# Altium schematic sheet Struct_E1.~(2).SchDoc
size 420 x 297 mm; Scale: 1:1; Разраб.: Иванов; Обозначение документа: АБВГ.123456.001 Э3; Пров.: Петров; Утв.: Сидоров; Наименование организации: ОАО "Концерн "МПО-Гидроприбор"; Перв. применение: АБВГ.123456.000; Наименование изделия 1: Плата; Наименование изделия 2: Схема электрическая; Наименование изделия 3: принципиальная; Нач. отд.: Нач. отд.; Фамилия нач. отд.: Сидоров
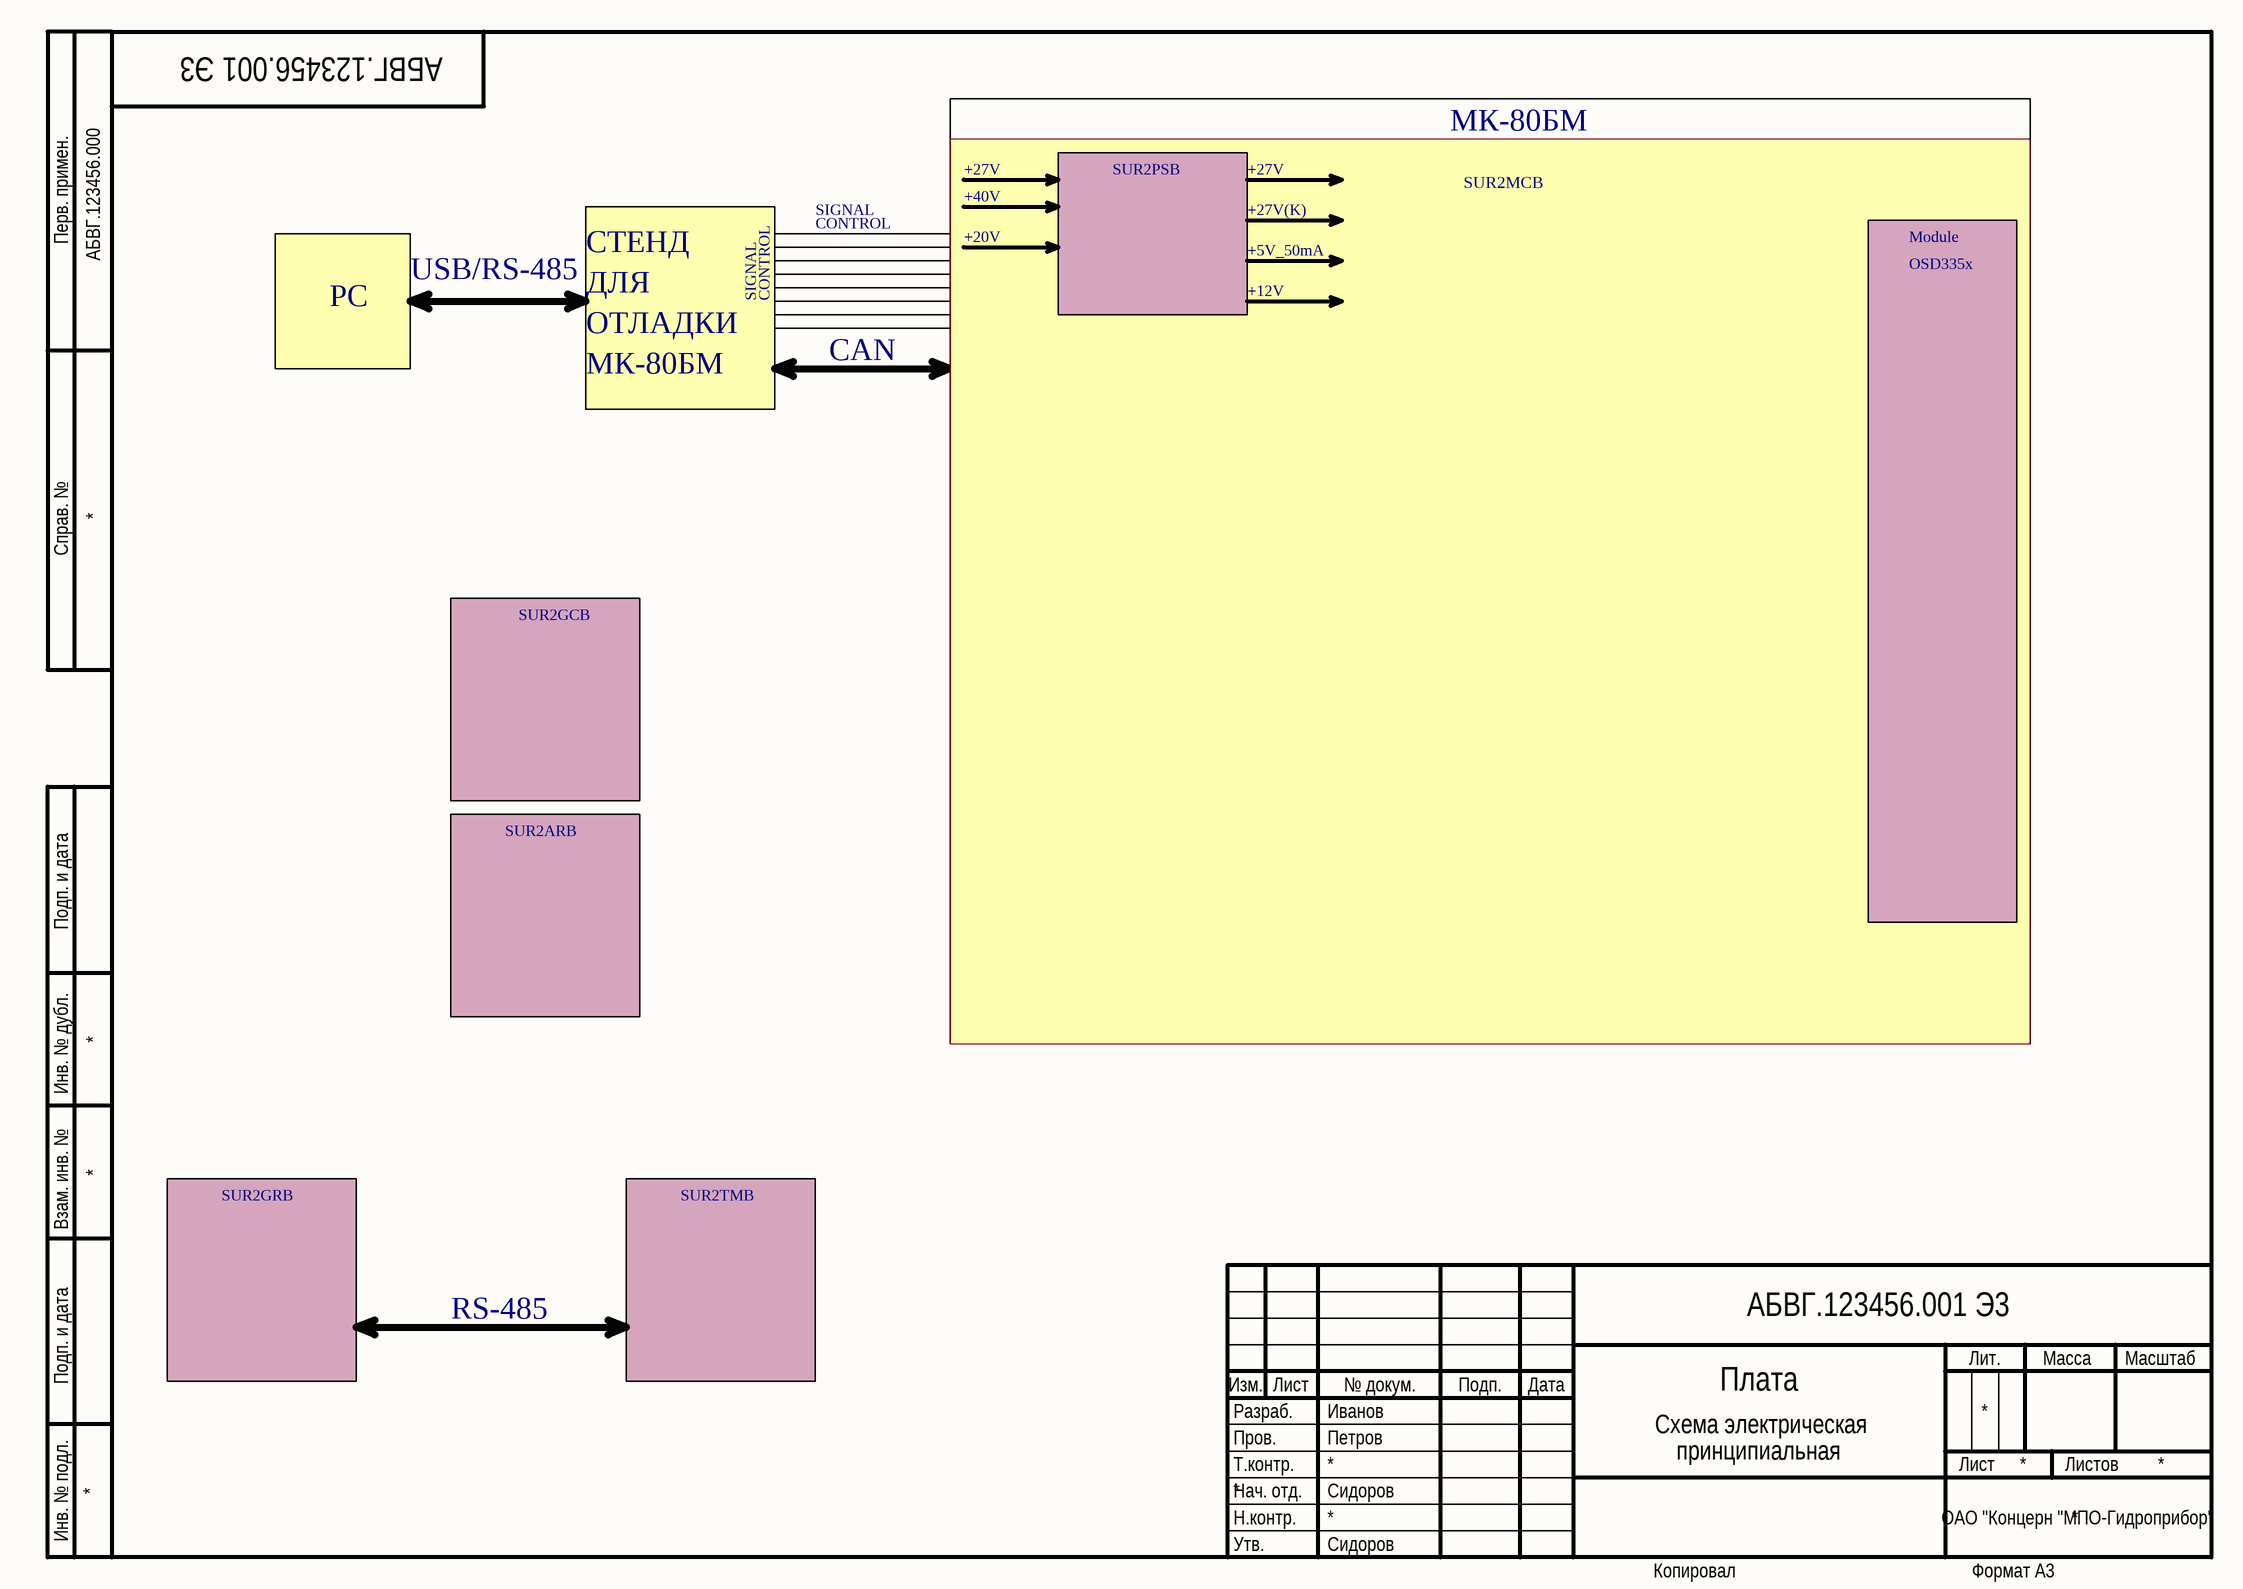
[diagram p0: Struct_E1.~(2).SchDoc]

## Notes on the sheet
- +27V
- SUR2PSB
- МК-80БМ
- SUR2MCB
- СТЕНД
- SIGNAL
- CONTROL
- +40V
- +20V
- +27V(K)
- +5V_50mA
- Module
- PC
- USB/RS-485
- ДЛЯ
- +12V
- OSD335x
- ОТЛАДКИ
- CAN
- SUR2GCB
- SUR2ARB
- SUR2GRB
- SUR2TMB
- RS-485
